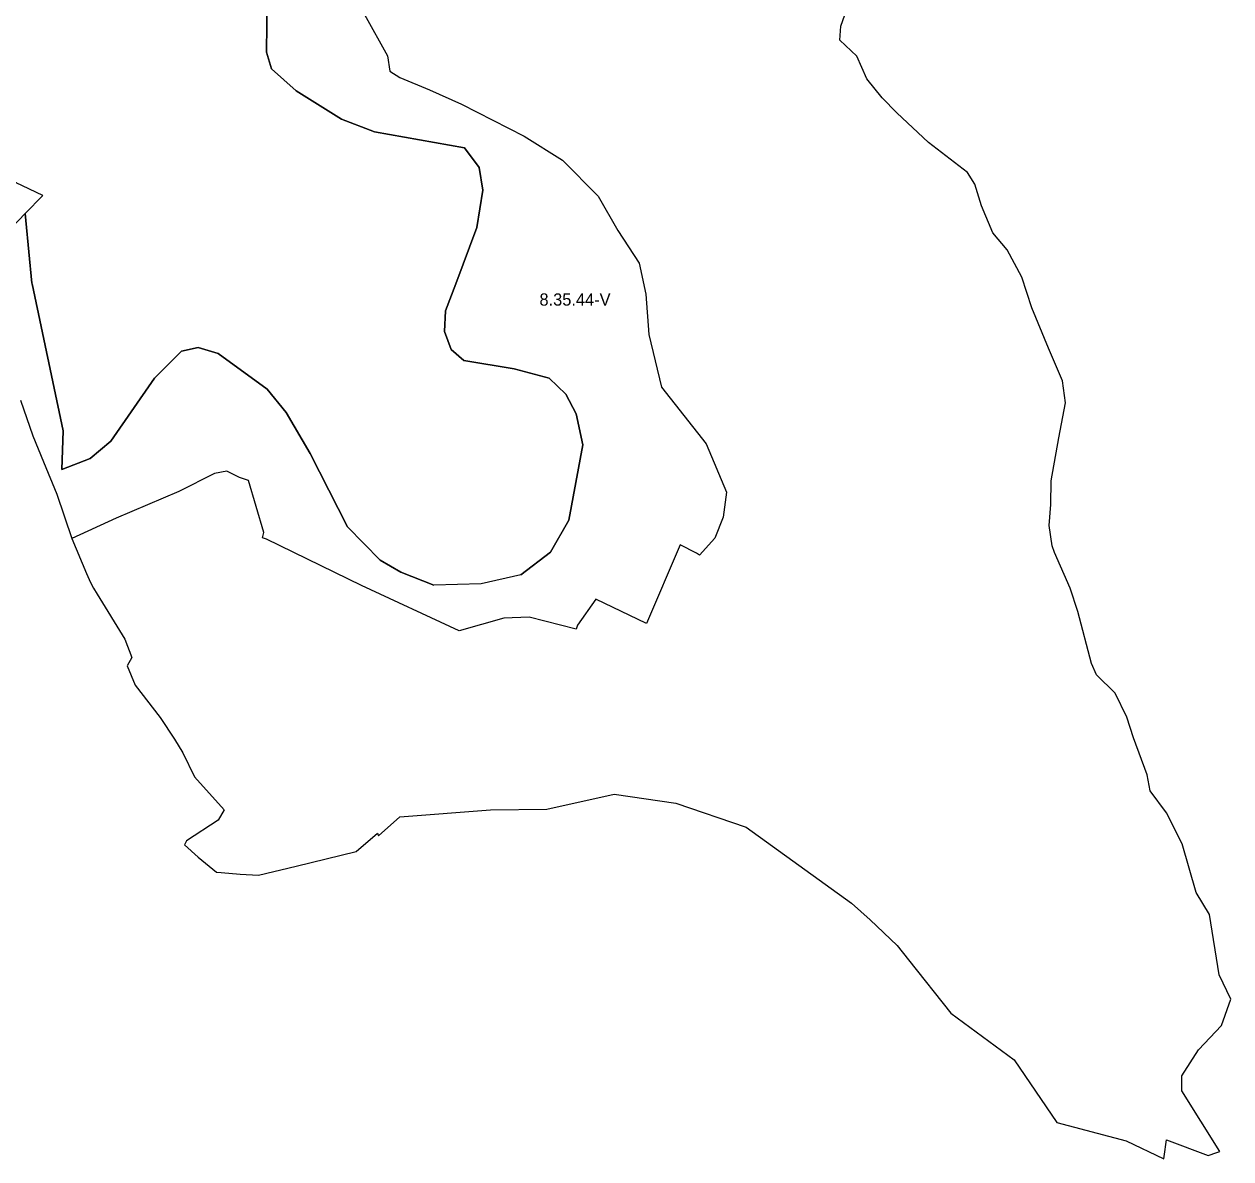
# Model space of a CAD drawing. Extents: x -547623 to -533936, y -1096714 to -1086523.
# Drawn here: x -544574 to -543590, y -1096714 to -1095788 of the extents above; entities that cross this region are included whole.
import ezdxf

# ---------------------------------------------------------------- set-up
doc = ezdxf.new("R2010")
doc.units = 0
doc.layers.add('Vrstva 27', color=7, linetype='Continuous')
doc.layers.add('Vrstva 28', color=7, linetype='Continuous')

msp = doc.modelspace()

# ---------------------------------------------------------------- linework, layer by layer
at = {"layer": 'Vrstva 28'}
for p, q in [((-544376, -1095766), (-544376.5, -1095811)), ((-544376.5, -1095811), (-544376, -1095766)), ((-544376.5, -1095811), (-544372.5, -1095824.5)), ((-544372.5, -1095824.5), (-544376.5, -1095811)), ((-544372.5, -1095824.5), (-544352.5, -1095842.5)), ((-544352.5, -1095842.5), (-544372.5, -1095824.5)), ((-544352.5, -1095842.5), (-544315.5, -1095865.5)), ((-544315.5, -1095865.5), (-544352.5, -1095842.5)), ((-544315.5, -1095865.5), (-544288.5, -1095876)), ((-544288.5, -1095876), (-544315.5, -1095865.5)), ((-544288.5, -1095876), (-544215, -1095889)), ((-544215, -1095889), (-544288.5, -1095876)), ((-544215, -1095889), (-544203, -1095905)), ((-544203, -1095905), (-544215, -1095889)), ((-544203, -1095905), (-544200, -1095923.5)), ((-544200, -1095923.5), (-544203, -1095905)), ((-544200, -1095923.5), (-544205, -1095954)), ((-544205, -1095954), (-544200, -1095923.5)), ((-544572.85, -1095948.38), (-544573.4, -1095942.66)), ((-544573.4, -1095942.66), (-544572.85, -1095948.38)), ((-544568, -1095999.5), (-544572.85, -1095948.38)), ((-544572.85, -1095948.38), (-544568, -1095999.5)), ((-544205, -1095954), (-544222.25, -1096000)), ((-544222.25, -1096000), (-544205, -1095954)), ((-544567.89, -1096000), (-544568, -1095999.5)), ((-544568, -1095999.5), (-544567.89, -1096000)), ((-544542.5, -1096120), (-544567.89, -1096000)), ((-544567.89, -1096000), (-544542.5, -1096120)), ((-544222.25, -1096000), (-544230.5, -1096022)), ((-544230.5, -1096022), (-544222.25, -1096000)), ((-544230.5, -1096022), (-544231.5, -1096039)), ((-544231.5, -1096039), (-544230.5, -1096022)), ((-544231.5, -1096039), (-544226, -1096053.5)), ((-544226, -1096053.5), (-544231.5, -1096039)), ((-544432.5, -1096052), (-544446, -1096055)), ((-544446, -1096055), (-544432.5, -1096052)), ((-544416, -1096057), (-544432.5, -1096052)), ((-544432.5, -1096052), (-544416, -1096057)), ((-544446, -1096055), (-544468, -1096077)), ((-544468, -1096077), (-544446, -1096055)), ((-544376, -1096086), (-544416, -1096057)), ((-544416, -1096057), (-544376, -1096086)), ((-544226, -1096053.5), (-544215.5, -1096062.5)), ((-544215.5, -1096062.5), (-544226, -1096053.5)), ((-544215.5, -1096062.5), (-544174.5, -1096069.5)), ((-544174.5, -1096069.5), (-544215.5, -1096062.5)), ((-544174.5, -1096069.5), (-544146, -1096077)), ((-544146, -1096077), (-544174.5, -1096069.5)), ((-544468, -1096077), (-544503.5, -1096128.5)), ((-544503.5, -1096128.5), (-544468, -1096077)), ((-544146, -1096077), (-544132.5, -1096090)), ((-544132.5, -1096090), (-544146, -1096077)), ((-544360.5, -1096105), (-544376, -1096086)), ((-544376, -1096086), (-544360.5, -1096105)), ((-544132.5, -1096090), (-544124, -1096106)), ((-544124, -1096106), (-544132.5, -1096090)), ((-544341, -1096138.5), (-544360.5, -1096105)), ((-544360.5, -1096105), (-544341, -1096138.5)), ((-544124, -1096106), (-544118.5, -1096131.5)), ((-544118.5, -1096131.5), (-544124, -1096106)), ((-544543.5, -1096151.5), (-544542.5, -1096120)), ((-544542.5, -1096120), (-544543.5, -1096151.5)), ((-544503.5, -1096128.5), (-544520.5, -1096142.5)), ((-544520.5, -1096142.5), (-544503.5, -1096128.5)), ((-544310.5, -1096198.5), (-544341, -1096138.5)), ((-544341, -1096138.5), (-544310.5, -1096198.5)), ((-544118.5, -1096131.5), (-544130, -1096193)), ((-544130, -1096193), (-544118.5, -1096131.5)), ((-544520.5, -1096142.5), (-544543.5, -1096151.5)), ((-544543.5, -1096151.5), (-544520.5, -1096142.5)), ((-544284, -1096225.5), (-544310.5, -1096198.5)), ((-544310.5, -1096198.5), (-544284, -1096225.5)), ((-544130, -1096193), (-544145, -1096219)), ((-544145, -1096219), (-544130, -1096193)), ((-544145, -1096219), (-544169, -1096237.5)), ((-544169, -1096237.5), (-544145, -1096219)), ((-544267, -1096235.5), (-544284, -1096225.5)), ((-544284, -1096225.5), (-544267, -1096235.5)), ((-544240, -1096246), (-544267, -1096235.5)), ((-544267, -1096235.5), (-544240, -1096246))]:
    msp.add_line(p, q, dxfattribs=at)
for points in [[(-544315.54, -1095746.06), (-544277.8, -1095813.87), (-544276.09, -1095826.36), (-544267.78, -1095831.66), (-544243.68, -1095841.7), (-544217.45, -1095853.43), (-544166.34, -1095879.46), (-544135.13, -1095899.06), (-544106, -1095928.39), (-544090.08, -1095956.43), (-544072.63, -1095983.03), (-544067.22, -1096008.4), (-544064.78, -1096041.36), (-544054.26, -1096084.4), (-544017.99, -1096130.6), (-544001.2, -1096170.03), (-544004.01, -1096190.41), (-544010.69, -1096207.56), (-544023.26, -1096221.46), (-544025.67, -1096219.81), (-544039.06, -1096213.19), (-544066.51, -1096277.38), (-544107.89, -1096257.33), (-544122.98, -1096278.72), (-544123.95, -1096282.02), (-544162.22, -1096272.16), (-544182.84, -1096273.01), (-544219.49, -1096283.3), (-544298.98, -1096246.18), (-544376.6, -1096208.51), (-544379.89, -1096207.34), (-544378.86, -1096202.98), (-544391.21, -1096160.54), (-544398.56, -1096158.18), (-544409.08, -1096152.96), (-544418.99, -1096154.91), (-544448.17, -1096169.47), (-544499.37, -1096191.19), (-544535.52, -1096207.97), (-544523.44, -1096236.54), (-544520.19, -1096243.71), (-544517.79, -1096248.57), (-544514.87, -1096253.31), (-544492.24, -1096290.07), (-544486.55, -1096305.02), (-544490.28, -1096311.9), (-544483.8, -1096327.66), (-544463.44, -1096354.05), (-544451.79, -1096371.74), (-544444.92, -1096382.79), (-544435.31, -1096402.39), (-544411.05, -1096429.44), (-544416.08, -1096437.76), (-544441.88, -1096454.65), (-544443.64, -1096458.04), (-544432.27, -1096468.08), (-544417.32, -1096480.27), (-544413.71, -1096480.59), (-544398.23, -1096481.97), (-544383.25, -1096482.82), (-544352.29, -1096475.34), (-544303.56, -1096463.4), (-544286.08, -1096448.31), (-544285.09, -1096450.5), (-544267.87, -1096435), (-544193.87, -1096429.52), (-544147.83, -1096428.89), (-544093, -1096416.56), (-544042.65, -1096424.03), (-543985.28, -1096443.66), (-543899.23, -1096505.63), (-543883.96, -1096519.14), (-543862.15, -1096540.21), (-543852.81, -1096551.75), (-543818.24, -1096595.48), (-543766.66, -1096633.53), (-543731.86, -1096684.76), (-543675.2, -1096699.68), (-543644.53, -1096714.33), (-543644.21, -1096712.32), (-543642.35, -1096698.73), (-543608.19, -1096711.59), (-543601.08, -1096709)], [(-544376, -1095766), (-544376.5, -1095811), (-544372.5, -1095824.5), (-544352.5, -1095842.5), (-544315.5, -1095865.5), (-544288.5, -1095876), (-544215, -1095889), (-544203, -1095905), (-544200, -1095923.5), (-544205, -1095954), (-544222.25, -1096000), (-544230.5, -1096022), (-544231.5, -1096039), (-544226, -1096053.5), (-544215.5, -1096062.5), (-544174.5, -1096069.5), (-544146, -1096077), (-544132.5, -1096090), (-544124, -1096106), (-544118.5, -1096131.5), (-544130, -1096193), (-544145, -1096219), (-544169, -1096237.5), (-544201.5, -1096245), (-544240, -1096246), (-544267, -1096235.5), (-544284, -1096225.5), (-544310.5, -1096198.5), (-544341, -1096138.5), (-544360.5, -1096105), (-544376, -1096086), (-544416, -1096057), (-544432.5, -1096052), (-544446, -1096055), (-544468, -1096077), (-544503.5, -1096128.5), (-544520.5, -1096142.5), (-544543.5, -1096151.5), (-544542.5, -1096120), (-544567.89, -1096000), (-544568, -1095999.5), (-544572.85, -1095948.38), (-544573.4, -1095942.66)], [(-544577.33, -1096095.02), (-544567.34, -1096124.06), (-544558.61, -1096145.37), (-544547.78, -1096171.8), (-544535.52, -1096207.97), (-544523.44, -1096236.54), (-544520.19, -1096243.71), (-544517.79, -1096248.57), (-544514.87, -1096253.31), (-544492.24, -1096290.07), (-544486.55, -1096305.02), (-544490.28, -1096311.9), (-544483.8, -1096327.66), (-544463.44, -1096354.05), (-544451.79, -1096371.74), (-544444.92, -1096382.79), (-544435.31, -1096402.39), (-544411.05, -1096429.44), (-544416.08, -1096437.76), (-544441.88, -1096454.65), (-544443.64, -1096458.04), (-544432.27, -1096468.08), (-544417.32, -1096480.27), (-544413.71, -1096480.59), (-544398.23, -1096481.97), (-544383.25, -1096482.82), (-544352.29, -1096475.34), (-544303.56, -1096463.4), (-544286.08, -1096448.31), (-544285.09, -1096450.5), (-544267.87, -1096435), (-544193.87, -1096429.52), (-544147.83, -1096428.89), (-544093, -1096416.56), (-544042.65, -1096424.03), (-543985.28, -1096443.66), (-543899.23, -1096505.63), (-543883.96, -1096519.14), (-543862.15, -1096540.21), (-543852.81, -1096551.75), (-543818.24, -1096595.48), (-543766.66, -1096633.53), (-543731.86, -1096684.76), (-543675.2, -1096699.68), (-543644.53, -1096714.33), (-543644.21, -1096712.32), (-543642.35, -1096698.73), (-543608.19, -1096711.59), (-543601.08, -1096709), (-543598.83, -1096708.18), (-543629.73, -1096658.78), (-543629.66, -1096646.45), (-543616.03, -1096625.35), (-543597.28, -1096605.56), (-543589.75, -1096584.02), (-543599.19, -1096564.07), (-543607.18, -1096514.71), (-543618.05, -1096496.91), (-543629.42, -1096457.05), (-543642.15, -1096431.74), (-543655.63, -1096413.87), (-543657.96, -1096400.72), (-543669.08, -1096370.74), (-543674.53, -1096353.69), (-543684.08, -1096334.19), (-543699.36, -1096319.08), (-543703.33, -1096310.05), (-543714.74, -1096267.62), (-543720.83, -1096248.35), (-543733.72, -1096219.3), (-543735.43, -1096213.79), (-543738.09, -1096197.38), (-543736.76, -1096180.02), (-543736.37, -1096160.85), (-543730.23, -1096125.81), (-543724.71, -1096097.1), (-543727.15, -1096079.27), (-543738.52, -1096052.64), (-543752.25, -1096019.5), (-543760.39, -1095994.67), (-543772.34, -1095972.36), (-543784.01, -1095958.33), (-543793.12, -1095936.43), (-543798.53, -1095918.76), (-543804.57, -1095909.2), (-543836.41, -1095884.72), (-543862.37, -1095860.36), (-543874.32, -1095848.19), (-543886.82, -1095832.65), (-543894.92, -1095814.04), (-543908.87, -1095801.15), (-543907.92, -1095789.75), (-543901.68, -1095771.97)], [(-544573.4, -1095942.66), (-544559.19, -1095927.93), (-544575.77, -1095919.94), (-544575.73, -1095920.01), (-544575.77, -1095919.94), (-544580.8, -1095917.52), (-544604.43, -1095902.72), (-544589.76, -1095959.63), (-544573.4, -1095942.66)]]:
    msp.add_lwpolyline(points, dxfattribs=at)

# ---------------------------------------------------------------- texts
at = {"layer": 'Vrstva 27'}
msp.add_text('8.35.44-V', height=10, dxfattribs=at).set_placement((-544153.88, -1096017.82))

doc.saveas('drawing.dxf')
